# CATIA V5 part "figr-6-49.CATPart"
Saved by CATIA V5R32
Part number: Part1
Bounding box of the stored display mesh (mm): x -54.76 to 54.76, y -32.885 to 32.885, z 0 to 59
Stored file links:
  D:\PROJECTS\Project 2022\CATIA V5 6R 2022\Resources\Part Files\c06_catia_v5_6r2022_prt\figr-6-49.CATPart
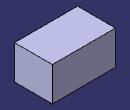
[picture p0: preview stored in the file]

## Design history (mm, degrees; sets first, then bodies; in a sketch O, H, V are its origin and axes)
Body1 (main body)
  Sketch1 on xy-plane, origin (0, 0, 0), H (1, 0, 0), V (0, 1, 0)
    line L1 (-54.7599, 32.8853) -> (54.7599, 32.8853)
    line L2 (54.7599, 32.8853) -> (54.7599, -32.8853)
    line L3 (54.7599, -32.8853) -> (-54.7599, -32.8853)
    line L4 (-54.7599, -32.8853) -> (-54.7599, 32.8853)
    axis line L5 (54.7599, -32.8853) -> (-54.7599, 32.8853)
    horizontal: L1 H, L3 H
    vertical: L2 V, L4 V
    midpoint: O L5
  Pad1: profile Sketch1, direction (0, 0, 1), length 59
